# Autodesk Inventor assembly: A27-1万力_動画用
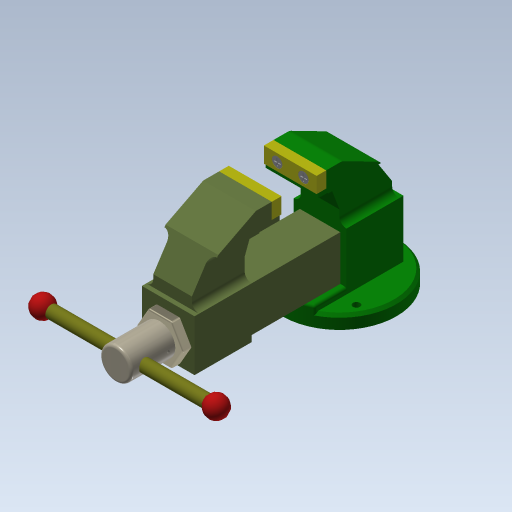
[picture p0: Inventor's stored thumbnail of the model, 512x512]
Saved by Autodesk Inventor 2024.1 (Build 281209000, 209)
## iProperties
Created: 2008-07
Part Number: A27-1万力_動画用
Document SubType Name: Assembly
Designer: y-shimohigashi
Stock Number: A24-1万力
ドキュメント番号: 19
目的: プロパティコピー練習
Author: y-shimohigashi
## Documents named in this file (5)
- C:\Users\h-sato\Desktop\R2024\Inventor2024基礎コース\練習問題\練習問題-27\A27-1万力_動画用.iam
- C:\Users\h-sato\Desktop\R2024\Inventor2024基礎コース\練習問題\練習問題-27\A27-12.iam
- C:\Users\h-sato\Desktop\R2024\Inventor2024基礎コース\練習問題\練習問題-27\A27-13.iam
- C:\Users\h-sato\Desktop\R2024\Inventor2024基礎コース\練習問題\練習問題-27\A27-14.iam
- C:\Users\h-sato\Desktop\R2024\Inventor2024基礎コース\練習問題\練習問題-27\P27-10ボス.ipt
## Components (5 placed, 4 different names)
1. A27-12:1 [sub-assembly] — メイト:5, メイト:6, メイト:7
2. A27-13:1 [sub-assembly] — メイト:5, メイト:6, メイト:7, 挿入:1
3. A27-14:1 [sub-assembly] — 挿入:1, 挿入:2, 挿入:3
4. P27-10ボス:1 — 挿入:2
5. P27-10ボス:2 — 挿入:3
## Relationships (6: Mate 3, Insert 3)
- メイト:5 [Mate]: A27-12:1 ↔ A27-13:1
- メイト:6 [Mate]: A27-12:1 ↔ A27-13:1
- メイト:7 [Mate]: A27-12:1 ↔ A27-13:1
- 挿入:1 [Insert]: A27-13:1 ↔ A27-14:1
- 挿入:2 [Insert]: A27-14:1 ↔ P27-10ボス:1
- 挿入:3 [Insert]: A27-14:1 ↔ P27-10ボス:2
